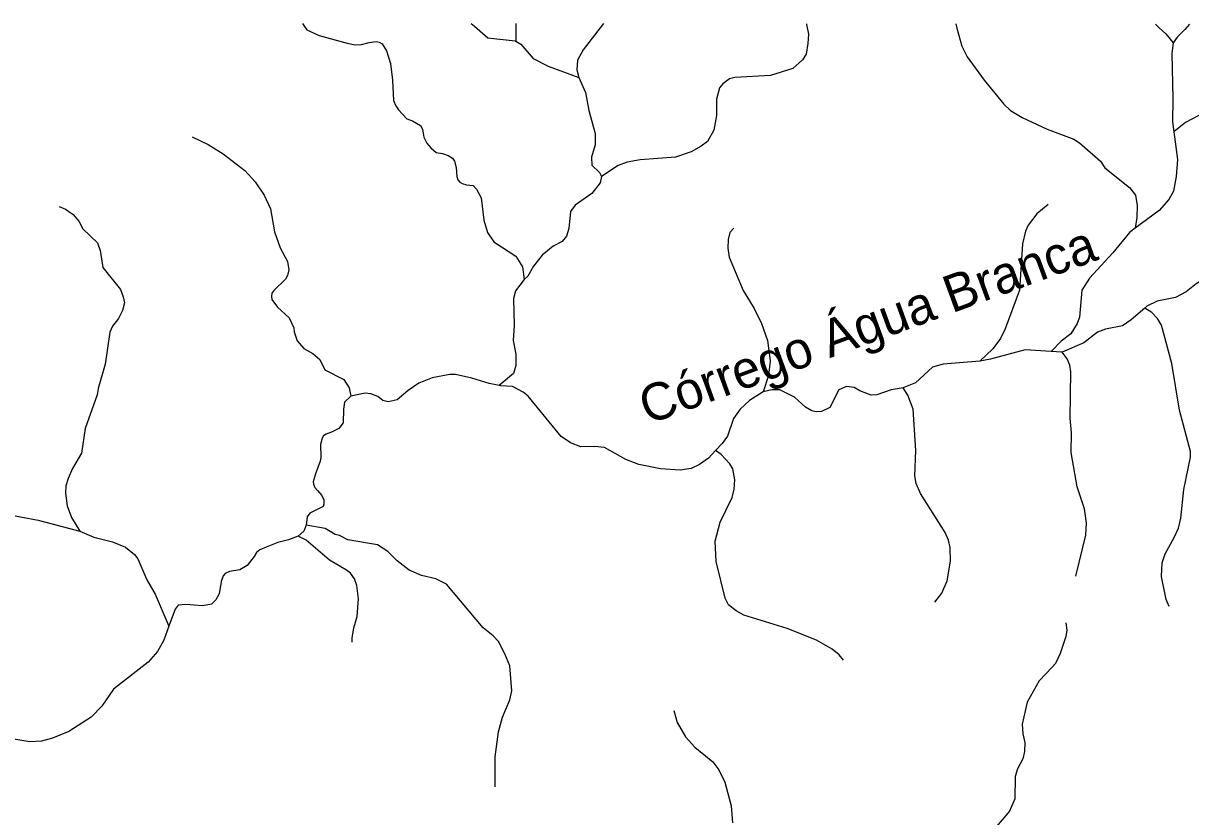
# Model space of a CAD drawing. Extents: x 500 to 555.2, y 9115.7 to 9171.
# Drawn here: x 543.48 to 549.76, y 9166.69 to 9170.95 of the extents above; entities that cross this region are included whole.
import ezdxf
from ezdxf.enums import TextEntityAlignment as Align

# ---------------------------------------------------------------- set-up
doc = ezdxf.new("R2010")
doc.units = 0
doc.header["$LTSCALE"] = 0.064
doc.layers.add('61', color=7, linetype='Continuous')
doc.layers.add('7', color=7, linetype='Continuous', lineweight=25)

msp = doc.modelspace()

# ---------------------------------------------------------------- linework, layer by layer
at = {"layer": '7'}
for points in [[(544.9844, 9170.9534), (544.9922, 9170.9414), (545.0074, 9170.9179), (545.0742, 9170.888), (545.2251, 9170.8468), (545.2682, 9170.8382), (545.3022, 9170.8401), (545.3426, 9170.851), (545.381, 9170.8562), (545.3962, 9170.853), (545.4118, 9170.8433), (545.4358, 9170.8049), (545.457, 9170.7367), (545.4685, 9170.6481), (545.4733, 9170.5394), (545.4862, 9170.5101), (545.501, 9170.4881), (545.5446, 9170.4408), (545.5762, 9170.4302), (545.6188, 9170.404), (545.6291, 9170.3852), (545.6364, 9170.342), (545.6528, 9170.3101), (545.6736, 9170.2841), (545.7033, 9170.2596), (545.737, 9170.2545), (545.7664, 9170.2432), (545.7912, 9170.2281), (545.8017, 9170.2128), (545.8092, 9170.1793), (545.813, 9170.1305), (545.8194, 9170.1127), (545.8297, 9170.0999), (545.8425, 9170.0922), (545.8651, 9170.0862), (545.901, 9170.0822), (545.9197, 9170.0614), (545.9438, 9170.0155), (545.9592, 9169.8954), (545.9777, 9169.83), (546.013, 9169.7791), (546.131, 9169.7014), (546.1672, 9169.6451), (546.1754, 9169.5772)], [(545.8913, 9170.9526), (545.9088, 9170.9376), (545.98, 9170.8764), (546.127, 9170.8586), (546.1302, 9170.8568)], [(546.13, 9170.9524), (546.13, 9170.9459), (546.1302, 9170.8568)], [(546.6009, 9170.952), (546.4921, 9170.8105), (546.4628, 9170.7551), (546.4584, 9170.7029), (546.4684, 9170.6629)], [(547.6923, 9170.9509), (547.6929, 9170.9469), (547.7037, 9170.8946), (547.6986, 9170.8459), (547.6909, 9170.7877), (547.6713, 9170.758), (547.6184, 9170.7113), (547.4986, 9170.6728), (547.3076, 9170.6624), (547.2789, 9170.6544), (547.2425, 9170.6291), (547.2249, 9170.6075), (547.2093, 9170.5455), (547.2089, 9170.4585), (547.1942, 9170.3798), (547.1599, 9170.3191), (547.1261, 9170.2929), (547.0727, 9170.2637), (546.988, 9170.2349), (546.7978, 9170.2201), (546.7283, 9170.2069), (546.6811, 9170.1898), (546.5901, 9170.1309)], [(548.4937, 9170.9501), (548.5001, 9170.9268), (548.5263, 9170.8313), (548.5552, 9170.7734), (548.6471, 9170.6475), (548.752, 9170.519), (548.789, 9170.4854), (548.8514, 9170.4477), (548.9845, 9170.3846), (549.129, 9170.3301), (549.1591, 9170.3119), (549.2718, 9170.2123), (549.2954, 9170.1774), (549.4276, 9170.0711), (549.459, 9170.0295), (549.4692, 9169.975), (549.4675, 9169.9101), (549.4579, 9169.8518)], [(549.5679, 9170.949), (549.5878, 9170.9299), (549.6227, 9170.8965), (549.6618, 9170.8479)], [(549.7508, 9170.9488), (549.7241, 9170.9211), (549.6833, 9170.8788), (549.6618, 9170.8479)], [(546.1302, 9170.8568), (546.1568, 9170.8415), (546.2231, 9170.7649), (546.3051, 9170.7236), (546.4684, 9170.6629)], [(549.6618, 9170.8479), (549.6558, 9170.7921), (549.661, 9170.5471), (549.6578, 9170.4244), (549.6652, 9170.3704)], [(546.4684, 9170.6629), (546.5051, 9170.5825), (546.5229, 9170.4856), (546.5574, 9170.3609), (546.556, 9170.3004), (546.5365, 9170.2348), (546.5381, 9170.1911), (546.5796, 9170.1511), (546.5901, 9170.1309)], [(551.2528, 9170.5351), (551.2266, 9170.5381), (551.0559, 9170.6053), (550.8716, 9170.6399), (550.7918, 9170.6382), (550.7222, 9170.6297), (550.6327, 9170.604), (550.4655, 9170.5793), (550.1025, 9170.5561), (549.9793, 9170.5317), (549.8639, 9170.4921), (549.7285, 9170.4197), (549.6652, 9170.3704)], [(544.3919, 9170.3429), (544.4783, 9170.3017), (544.5582, 9170.2526), (544.6739, 9170.1634), (544.7303, 9170.1018), (544.7779, 9170.0297), (544.8122, 9169.9559), (544.8341, 9169.8331), (544.8649, 9169.7461), (544.9039, 9169.6744), (544.9108, 9169.628), (544.9042, 9169.5974), (544.8923, 9169.5783), (544.8299, 9169.5179), (544.8196, 9169.5025), (544.817, 9169.4846), (544.82, 9169.4686), (544.8502, 9169.4279), (544.9124, 9169.3702), (544.9385, 9169.3176), (544.939, 9169.296), (544.956, 9169.2468), (544.9924, 9169.2053), (545.0399, 9169.1793), (545.078, 9169.1473), (545.1046, 9169.0917), (545.2064, 9169.0385), (545.2352, 9168.9952), (545.2447, 9168.9505)], [(549.6652, 9170.3704), (549.6857, 9170.2217), (549.6791, 9170.1298), (549.6639, 9170.0506), (549.6387, 9170.0072), (549.5877, 9169.9483), (549.4579, 9169.8518)], [(546.5901, 9170.1309), (546.584, 9170.0962), (546.5396, 9170.0397), (546.4496, 9169.9771), (546.4236, 9169.9431), (546.4148, 9169.851), (546.4032, 9169.8101), (546.3791, 9169.7809), (546.3308, 9169.7554), (546.2729, 9169.7071), (546.2252, 9169.6482), (546.1949, 9169.5954), (546.1754, 9169.5772)], [(543.6773, 9169.9683), (543.711, 9169.9542), (543.7528, 9169.9264), (543.7823, 9169.8903), (543.8047, 9169.8482), (543.8838, 9169.7736), (543.8969, 9169.7335), (543.9121, 9169.6411), (544.0069, 9169.523), (544.0215, 9169.4841), (544.0274, 9169.4513), (544.0182, 9169.41), (543.9959, 9169.368), (543.9631, 9169.3266), (543.9497, 9169.2933), (543.9249, 9169.1222), (543.8858, 9168.9914), (543.8811, 9168.9566), (543.8169, 9168.7755), (543.797, 9168.6443), (543.7495, 9168.5616), (543.725, 9168.5075), (543.7137, 9168.4678), (543.7103, 9168.4285), (543.7203, 9168.3605), (543.7435, 9168.2982), (543.7873, 9168.2238)], [(548.9899, 9169.9796), (548.9291, 9169.9299), (548.8839, 9169.8679), (548.8693, 9169.8357), (548.8525, 9169.7683), (548.836, 9169.5197), (548.7594, 9169.3109), (548.7343, 9169.2605), (548.6925, 9169.2037), (548.6228, 9169.1382)], [(547.302, 9169.8522), (547.2798, 9169.8296), (547.2705, 9169.7922), (547.2696, 9169.7448), (547.2761, 9169.6974), (547.3522, 9169.5182), (547.4113, 9169.4201), (547.4499, 9169.3408), (547.482, 9169.2493), (547.4976, 9169.1397), (547.4872, 9169.0615), (547.4601, 9168.973)], [(549.4579, 9169.8518), (549.4271, 9169.8289), (549.3375, 9169.7192), (549.2126, 9169.5848), (549.1722, 9169.519), (549.1593, 9169.3735), (549.147, 9169.3412), (549.1116, 9169.2851), (549.0602, 9169.2451), (549.0062, 9169.1893)], [(550.6721, 9169.5541), (550.6718, 9169.5542), (550.3369, 9169.677), (550.249, 9169.6886), (550.1232, 9169.6711), (549.9334, 9169.623), (549.8449, 9169.5885), (549.7858, 9169.554), (549.7326, 9169.5111), (549.6756, 9169.4809), (549.5765, 9169.4606)], [(546.1754, 9169.5772), (546.1296, 9169.5162), (546.1179, 9169.4755), (546.1209, 9169.3303), (546.1165, 9169.249), (546.1311, 9169.1752), (546.131, 9169.1155), (546.1182, 9169.0724), (546.041, 9169.0071)], [(549.5765, 9169.4606), (549.5214, 9169.4329), (549.5093, 9169.4225)], [(549.5093, 9169.4225), (549.4374, 9169.3609), (549.3902, 9169.3283), (549.2979, 9169.309), (549.2556, 9169.2938), (549.1821, 9169.2373), (549.065, 9169.1861)], [(549.6399, 9167.8202), (549.6255, 9167.8571), (549.5999, 9167.9813), (549.6034, 9168.0547), (549.6187, 9168.1022), (549.6685, 9168.1894), (549.6908, 9168.2408), (549.7037, 9168.2933), (549.7188, 9168.4475), (549.7559, 9168.6226), (549.7547, 9168.652), (549.6968, 9168.8748), (549.6547, 9169.1253), (549.5988, 9169.332), (549.5778, 9169.3667), (549.5482, 9169.3993), (549.5093, 9169.4225)], [(549.0062, 9169.1893), (548.8672, 9169.1981), (548.6808, 9169.1479), (548.6228, 9169.1382)], [(549.065, 9169.1861), (549.0639, 9169.1856), (549.0062, 9169.1893)], [(549.1401, 9167.9829), (549.1934, 9168.2029), (549.1968, 9168.2696), (549.1853, 9168.3452), (549.1463, 9168.4628), (549.1141, 9168.6477), (549.1165, 9168.7526), (549.1084, 9168.8307), (549.1132, 9169.08), (549.1065, 9169.1161), (549.0928, 9169.1509), (549.065, 9169.1861)], [(548.6228, 9169.1382), (548.4261, 9169.1222), (548.3687, 9169.1061), (548.2781, 9169.0218), (548.2159, 9168.9955), (548.2119, 9168.9948)], [(546.041, 9169.0071), (545.9879, 9169.0171), (545.895, 9169.0472), (545.8071, 9169.0668), (545.7754, 9169.0666), (545.6813, 9169.0478), (545.6103, 9169.0193), (545.5518, 9168.9808), (545.4934, 9168.9304), (545.4449, 9168.9195), (545.4168, 9168.9274), (545.3896, 9168.9472), (545.3519, 9168.963), (545.3209, 9168.9651), (545.2447, 9168.9505)], [(547.2039, 9168.6572), (547.1664, 9168.6164), (547.1172, 9168.5824), (547.0719, 9168.5609), (547.0143, 9168.5519), (546.9087, 9168.5585), (546.7919, 9168.5834), (546.7223, 9168.609), (546.6063, 9168.6733), (546.5551, 9168.6798), (546.4795, 9168.6776), (546.4237, 9168.6992), (546.3735, 9168.7328), (546.1967, 9168.9504), (546.1708, 9168.9709), (546.1121, 9169.0009), (546.049, 9169.0056), (546.041, 9169.0071)], [(547.4601, 9168.973), (547.3867, 9168.926), (547.3352, 9168.8799), (547.3005, 9168.8301), (547.2674, 9168.7354), (547.2387, 9168.695), (547.2039, 9168.6572)], [(548.2119, 9168.9948), (548.1476, 9168.9835), (548.0699, 9168.9571), (548.0391, 9168.9558), (547.9788, 9168.9781), (547.9486, 9168.9963), (547.9077, 9169.0024), (547.8667, 9168.9847), (547.8184, 9168.8895), (547.7721, 9168.8681), (547.7447, 9168.8652), (547.7216, 9168.8703), (547.6873, 9168.8902), (547.6281, 9168.9442), (547.5481, 9168.9831), (547.5059, 9168.9846), (547.4601, 9168.973)], [(548.3816, 9167.8426), (548.4197, 9167.8914), (548.4487, 9167.9576), (548.4653, 9168.063), (548.4638, 9168.1374), (548.4559, 9168.1761), (548.4376, 9168.2167), (548.305, 9168.4259), (548.2806, 9168.4809), (548.2751, 9168.5217), (548.2799, 9168.6574), (548.266, 9168.88), (548.237, 9168.9555), (548.2119, 9168.9948)], [(542.5997, 9168.9394), (542.645, 9168.7589), (542.7261, 9168.5815), (542.7849, 9168.5207), (542.8351, 9168.4782), (542.9215, 9168.4315), (543.1163, 9168.3812), (543.1832, 9168.3547), (543.5638, 9168.2843), (543.7873, 9168.2238)], [(545.2447, 9168.9505), (545.2107, 9168.9183), (545.2045, 9168.8806), (545.2028, 9168.8067), (545.179, 9168.7763), (545.1401, 9168.7565), (545.1119, 9168.7462), (545.0965, 9168.736), (545.0898, 9168.7241), (545.0819, 9168.6892), (545.0837, 9168.6206), (545.0786, 9168.6004), (545.0534, 9168.5316), (545.0426, 9168.4899), (545.0438, 9168.4761), (545.0503, 9168.4591), (545.0657, 9168.4437), (545.0888, 9168.4155), (545.099, 9168.3925), (545.099, 9168.3694), (545.0948, 9168.3566), (545.0239, 9168.3217), (545.0094, 9168.3005), (545.0039, 9168.2567)], [(547.8917, 9167.5302), (547.8676, 9167.5599), (547.8305, 9167.5906), (547.7458, 9167.6379), (547.5877, 9167.7005), (547.3561, 9167.7736), (547.3137, 9167.7953), (547.2728, 9167.8276), (547.2561, 9167.8642), (547.2076, 9168.0617), (547.2007, 9168.1713), (547.2281, 9168.2718), (547.2926, 9168.4061), (547.304, 9168.4502), (547.3064, 9168.5005), (547.2957, 9168.5593), (547.2806, 9168.5866), (547.2334, 9168.6355), (547.2039, 9168.6572)], [(543.7873, 9168.2238), (543.863, 9168.1914), (543.9634, 9168.1678), (544.0343, 9168.1387), (544.0816, 9168.0998), (544.1005, 9168.0761), (544.1474, 9167.9628), (544.1936, 9167.8865), (544.2666, 9167.7141)], [(545.0039, 9168.2567), (544.9923, 9168.2242), (544.9612, 9168.1968)], [(546.019, 9166.8512), (546.0197, 9167.0113), (546.0375, 9167.1465), (546.0587, 9167.2253), (546.0979, 9167.3171), (546.1097, 9167.3671), (546.098, 9167.5), (546.0721, 9167.5644), (546.0373, 9167.6305), (546.0097, 9167.6627), (545.9553, 9167.7044), (545.7589, 9167.9398), (545.7004, 9167.9677), (545.6233, 9167.9858), (545.5575, 9168.015), (545.4934, 9168.0643), (545.4426, 9168.1151), (545.3879, 9168.1508), (545.2277, 9168.1774), (545.1835, 9168.2004), (545.1597, 9168.206), (545.1065, 9168.2388), (545.0039, 9168.2567)], [(544.9612, 9168.1968), (544.9094, 9168.1777), (544.8511, 9168.1629), (544.7888, 9168.1387), (544.7555, 9168.1233), (544.7376, 9168.1105), (544.7251, 9168.0879), (544.6868, 9168.0406), (544.6482, 9168.0157), (544.5914, 9168.0079), (544.5684, 9167.9976), (544.5581, 9167.9848), (544.5466, 9167.9539), (544.5361, 9167.8878), (544.5193, 9167.855), (544.4952, 9167.8316), (544.4465, 9167.8236), (544.3571, 9167.83), (544.3168, 9167.8263), (544.3, 9167.8056), (544.2666, 9167.7141)], [(545.2521, 9167.6278), (545.2507, 9167.6487), (545.26, 9167.7042), (545.2782, 9167.765), (545.2847, 9167.8613), (545.2772, 9167.9322), (545.2634, 9167.9679), (545.2417, 9167.9977), (545.2208, 9168.0155), (545.1296, 9168.0688), (545.0038, 9168.1764), (544.9612, 9168.1968)], [(544.2666, 9167.7141), (544.2393, 9167.6393), (544.205, 9167.577), (544.1546, 9167.5202), (543.9688, 9167.3752)], [(549.0852, 9167.7309), (549.0907, 9167.6926), (549.0849, 9167.6577), (549.0556, 9167.5672), (549.0292, 9167.5131), (549.0119, 9167.4943), (548.942, 9167.4205), (548.8772, 9167.3052), (548.8508, 9167.1871), (548.8539, 9167.1358), (548.8655, 9167.0894), (548.8641, 9167.0407), (548.8539, 9167.0002), (548.8256, 9166.9462), (548.8135, 9166.9067), (548.8112, 9166.7864), (548.7825, 9166.72), (548.7136, 9166.637)], [(543.9688, 9167.3752), (543.9059, 9167.2844), (543.8498, 9167.2255), (543.7298, 9167.1478), (543.6418, 9167.1119), (543.5822, 9167.0953), (543.5192, 9167.092), (543.3558, 9167.1182), (543.2379, 9167.1148), (543.207, 9167.1025), (543.1536, 9167.0569), (543.1094, 9167.0282)], [(546.9803, 9167.2605), (546.9978, 9167.1958), (547.0428, 9167.1188), (547.0931, 9167.0634), (547.1891, 9166.9853), (547.2216, 9166.9423), (547.2529, 9166.8761), (547.2878, 9166.7487), (547.2942, 9166.6572)]]:
    msp.add_lwpolyline(points, dxfattribs=at)

# ---------------------------------------------------------------- texts
at = {"layer": '61'}
msp.add_text('Córrego Água Branca', height=0.2, rotation=20.129, dxfattribs=at).set_placement((548.054, 9169.2406), align=Align.CENTER)

doc.saveas('drawing.dxf')
